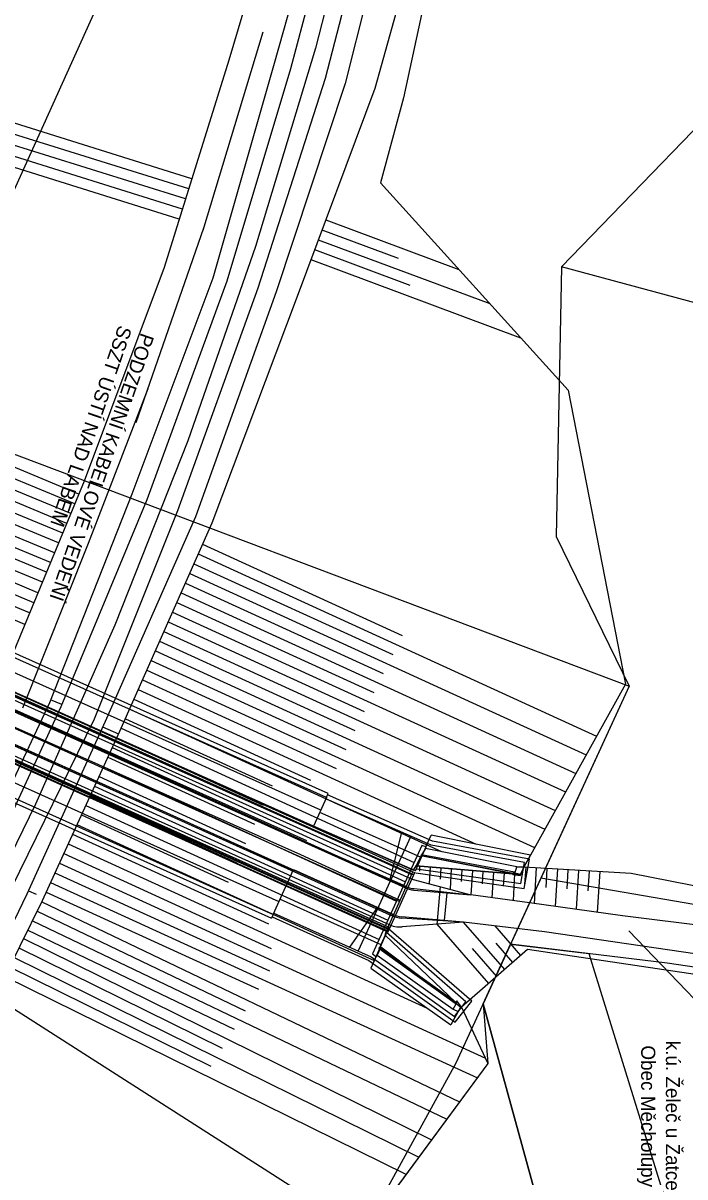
# Model space of a CAD drawing. Extents: x -801372 to -800991, y -1017235 to -1016862.
# Drawn here: x -801119.6 to -801072.7, y -1017078.6 to -1016996.8 of the extents above; entities that cross this region are included whole.
import ezdxf

# ---------------------------------------------------------------- set-up
doc = ezdxf.new("R2010")
doc.units = 0
for name, color, linetype in [('01 - nosná konstrukce', 7, 'Continuous'), ('02 - spodní stavba', 7, 'Continuous'), ('05a - kolej - svršek', 7, 'Continuous'), ('09 - stávající terén', 7, 'Continuous'), ('10 - nový terén', 7, 'Continuous'), ('15 - popisy', 7, 'Continuous'), ('16 - osy', 7, 'Continuous'), ('19 - katastr', 7, 'Continuous'), ('19b - katastr - hranice SŽDC', 7, 'Continuous'), ('19b - katastr popisy', 7, 'Continuous'), ('21g - SZDC', 7, 'Continuous'), ('26 - obvod_stavby', 7, 'Continuous'), ('27 - dočasné zábory', 7, 'Continuous'), ('Vrstva 1 - kolej', 7, 'Continuous'), ('Vrstva 48 - svahy', 7, 'Continuous')]:
    doc.layers.add(name, color=color, linetype=linetype)

msp = doc.modelspace()

# ---------------------------------------------------------------- linework, layer by layer
for points in [[(-801079.49, -1017062.745), (-801060.39, -1017124.37)], [(-801086.965, -1017066.29), (-801072.61, -1017118.61)]]:
    msp.add_lwpolyline(points)
at = {"layer": '01 - nosná konstrukce'}
for p, q in [((-801141.511, -1017034.878), (-801092.044, -1017057.15)), ((-801141.489, -1017034.828), (-801092.021, -1017057.1)), ((-801143.243, -1017038.724), (-801093.775, -1017060.996)), ((-801143.22, -1017038.674), (-801093.753, -1017060.945)), ((-801092.021, -1017057.1), (-801093.775, -1017060.996))]:
    msp.add_line(p, q, dxfattribs=at)
at = {"layer": '02 - spodní stavba'}
for p, q in [((-801141.627, -1017035.135), (-801092.117, -1017057.424)), ((-801141.422, -1017034.679), (-801091.954, -1017056.95)), ((-801097.948, -1017051.409), (-801131.185, -1017036.524)), ((-801098.071, -1017051.683), (-801131.308, -1017036.798)), ((-801098.473, -1017052.582), (-801131.711, -1017037.697)), ((-801143.31, -1017038.874), (-801093.842, -1017061.145)), ((-801143.067, -1017038.435), (-801093.637, -1017060.689)), ((-801099.101, -1017053.983), (-801132.338, -1017039.098)), ((-801132.255, -1017038.823), (-801099.018, -1017053.686)), ((-801098.978, -1017053.709), (-801132.215, -1017038.824)), ((-801099.45, -1017054.763), (-801132.687, -1017039.878)), ((-801133.146, -1017040.902), (-801099.914, -1017055.737)), ((-801100.984, -1017057.895), (-801134.364, -1017042.851)), ((-801133.986, -1017042.769), (-801100.807, -1017057.665)), ((-801098.112, -1017051.774), (-801097.948, -1017051.409)), ((-801098.071, -1017051.683), (-801098.978, -1017053.709)), ((-801090.658, -1017055.067), (-801098.112, -1017051.774)), ((-801090.569, -1017054.778), (-801097.988, -1017051.501)), ((-801091.422, -1017055.91), (-801098.548, -1017052.762)), ((-801099.018, -1017053.686), (-801091.898, -1017056.845)), ((-801091.774, -1017056.891), (-801098.978, -1017053.709)), ((-801091.899, -1017057.164), (-801099.099, -1017053.983)), ((-801092.103, -1017054.428), (-801095.817, -1017062.559)), ((-801093.559, -1017057.485), (-801092.729, -1017054.152)), ((-801092.421, -1017057.988), (-801099.479, -1017054.87)), ((-801091.774, -1017056.891), (-801090.917, -1017054.952)), ((-801091.066, -1017055.291), (-801091.353, -1017055.786)), ((-801091.066, -1017055.291), (-801091.019, -1017055.182)), ((-801084.598, -1017056.601), (-801091.066, -1017055.291)), ((-801084.039, -1017056.299), (-801090.658, -1017055.067)), ((-801083.689, -1017056.059), (-801090.569, -1017054.778)), ((-801099.914, -1017055.737), (-801099.905, -1017055.716)), ((-801099.905, -1017055.716), (-801092.864, -1017058.972)), ((-801091.347, -1017055.752), (-801091.714, -1017056.522)), ((-801091.347, -1017055.752), (-801091.379, -1017055.802)), ((-801091.353, -1017055.786), (-801091.379, -1017055.802)), ((-801091.379, -1017055.802), (-801084.812, -1017057.096)), ((-801091.353, -1017055.786), (-801084.738, -1017057.07)), ((-801084.752, -1017056.98), (-801091.347, -1017055.752)), ((-801084.316, -1017057.786), (-801084.039, -1017056.299)), ((-801084.073, -1017058.124), (-801083.689, -1017056.059)), ((-801101.839, -1017059.964), (-801100.41, -1017056.785)), ((-801100.411, -1017056.785), (-801093.316, -1017059.972)), ((-801093.706, -1017061.206), (-801091.817, -1017057.012)), ((-801092.021, -1017057.1), (-801091.954, -1017056.95)), ((-801091.954, -1017056.95), (-801091.817, -1017057.012)), ((-801091.827, -1017057.007), (-801091.899, -1017057.164)), ((-801091.898, -1017056.845), (-801091.714, -1017056.522)), ((-801091.747, -1017057.031), (-801084.073, -1017058.124)), ((-801091.714, -1017056.522), (-801084.296, -1017057.142)), ((-801091.704, -1017056.734), (-801084.316, -1017057.786)), ((-801084.877, -1017057.154), (-801084.851, -1017057.028)), ((-801084.851, -1017057.028), (-801084.752, -1017056.98)), ((-801084.296, -1017057.142), (-801084.851, -1017057.028)), ((-801084.812, -1017057.096), (-801084.752, -1017056.98)), ((-801084.812, -1017057.096), (-801084.738, -1017057.07)), ((-801084.738, -1017057.07), (-801084.598, -1017056.601)), ((-801084.738, -1017057.07), (-801084.332, -1017057.125)), ((-801084.598, -1017056.601), (-801084.097, -1017056.612)), ((-801084.332, -1017057.125), (-801084.36, -1017057.216)), ((-801084.36, -1017057.216), (-801084.296, -1017057.142)), ((-801084.097, -1017056.612), (-801084.332, -1017057.125)), ((-801084.296, -1017057.142), (-801084.097, -1017056.612)), ((-801093.829, -1017061.114), (-801100.984, -1017057.895)), ((-801100.807, -1017057.665), (-801093.642, -1017060.883)), ((-801101.355, -1017058.887), (-801094.212, -1017062.097)), ((-801094.46, -1017059.458), (-801096.442, -1017062.279)), ((-801101.839, -1017059.964), (-801101.962, -1017060.237)), ((-801101.798, -1017059.872), (-801094.909, -1017062.968)), ((-801093.923, -1017061.442), (-801093.829, -1017061.114)), ((-801093.775, -1017060.996), (-801093.842, -1017061.145)), ((-801093.842, -1017061.145), (-801093.706, -1017061.206)), ((-801088.198, -1017066.161), (-801093.813, -1017061.259)), ((-801093.642, -1017060.883), (-801093.768, -1017061.156)), ((-801087.786, -1017066.123), (-801093.689, -1017060.986)), ((-801093.923, -1017061.442), (-801094.341, -1017062.39)), ((-801088.898, -1017066.209), (-801093.923, -1017061.442)), ((-801094.226, -1017062.286), (-801094.486, -1017062.862)), ((-801094.486, -1017062.862), (-801089.094, -1017066.688)), ((-801094.341, -1017062.39), (-801094.311, -1017062.284)), ((-801094.341, -1017062.39), (-801088.947, -1017066.254)), ((-801094.311, -1017062.284), (-801088.857, -1017066.199)), ((-801094.226, -1017062.286), (-801094.311, -1017062.284)), ((-801088.889, -1017066.293), (-801094.226, -1017062.286)), ((-801094.909, -1017062.968), (-801089.013, -1017067.191)), ((-801094.624, -1017063.095), (-801094.748, -1017063.369)), ((-801089.013, -1017067.191), (-801088.198, -1017066.161)), ((-801089.094, -1017066.688), (-801088.889, -1017066.293)), ((-801089.094, -1017066.688), (-801088.739, -1017066.845)), ((-801088.947, -1017066.254), (-801088.898, -1017066.209)), ((-801088.857, -1017066.199), (-801088.889, -1017066.293)), ((-801088.571, -1017066.549), (-801088.889, -1017066.293)), ((-801088.571, -1017066.549), (-801088.739, -1017066.845)), ((-801088.501, -1017066.544), (-801088.571, -1017066.549))]:
    msp.add_line(p, q, dxfattribs=at)
for points in [[(-801144.304, -1017041.012), (-801143.355, -1017038.895), (-801134.109, -1017043.043), (-801100.929, -1017057.938), (-801093.768, -1017061.156), (-801094.624, -1017063.095)], [(-801133.635, -1017041.989), (-801100.456, -1017056.885)], [(-801134.614, -1017044.17), (-801101.435, -1017059.065)], [(-801135.14, -1017045.342), (-801101.962, -1017060.237)], [(-801135.017, -1017045.068), (-801101.839, -1017059.964)], [(-801091.898, -1017056.845), (-801091.908, -1017056.832)], [(-801084.812, -1017057.096), (-801084.877, -1017057.154), (-801084.36, -1017057.216)], [(-801101.921, -1017060.146), (-801095.059, -1017063.229), (-801088.955, -1017067.602), (-801087.786, -1017066.123)], [(-801093.844, -1017061.123), (-801093.829, -1017061.114)], [(-801088.947, -1017066.254), (-801088.857, -1017066.199), (-801088.847, -1017066.095)], [(-801088.501, -1017066.544), (-801088.847, -1017066.095), (-801088.898, -1017066.209)]]:
    msp.add_lwpolyline(points, dxfattribs=at)
at = {"layer": '05a - kolej - svršek'}
for p, q in [((-801097.681, -1016985.202), (-801101.815, -1016999.87)), ((-801096.694, -1016985.292), (-801100.623, -1017000.081)), ((-801094.326, -1016985.96), (-801098.17, -1017000.765)), ((-801093.001, -1016986.187), (-801096.751, -1017001.133)), ((-801101.815, -1016999.87), (-801106.12, -1017014.918)), ((-801100.623, -1017000.081), (-801105.127, -1017015.126)), ((-801098.17, -1017000.765), (-801102.922, -1017015.627)), ((-801096.751, -1017001.133), (-801101.624, -1017015.873)), ((-801106.12, -1017014.918), (-801111.843, -1017030.203)), ((-801105.127, -1017015.126), (-801110.785, -1017030.615)), ((-801102.922, -1017015.627), (-801108.608, -1017031.382)), ((-801101.624, -1017015.873), (-801107.351, -1017031.811)), ((-801111.843, -1017030.203), (-801117.691, -1017044.978)), ((-801110.785, -1017030.615), (-801116.869, -1017045.275)), ((-801108.608, -1017031.382), (-801114.526, -1017046.136)), ((-801107.351, -1017031.811), (-801113.747, -1017046.297)), ((-801117.691, -1017044.978), (-801123.526, -1017057.407)), ((-801116.869, -1017045.275), (-801122.516, -1017057.485)), ((-801114.526, -1017046.136), (-801120.402, -1017058.145)), ((-801113.747, -1017046.297), (-801119.29, -1017058.542)), ((-801119.29, -1017058.542), (-801126.271, -1017073.005))]:
    msp.add_line(p, q, dxfattribs=at)
at = {"layer": '09 - stávající terén'}
for p, q in [((-801100.678, -1016984.915), (-801104.977, -1016999.48)), ((-801090.496, -1016986.553), (-801094.657, -1017001.481)), ((-801089.247, -1016986.662), (-801092.622, -1017002.134)), ((-801104.977, -1016999.48), (-801109.562, -1017014.148)), ((-801094.657, -1017001.481), (-801100.153, -1017016.222)), ((-801092.622, -1017002.134), (-801094.239, -1017008.166)), ((-801094.239, -1017008.166), (-801080.961, -1017022.847)), ((-801109.562, -1017014.148), (-801115.218, -1017029.281)), ((-801100.153, -1017016.222), (-801106.182, -1017032.263)), ((-801080.961, -1017022.847), (-801076.897, -1017043.673)), ((-801115.218, -1017029.281), (-801121.19, -1017043.671)), ((-801106.182, -1017032.263), (-801112.715, -1017047.005)), ((-801076.897, -1017043.673), (-801084.097, -1017056.612)), ((-801112.715, -1017047.005), (-801118.207, -1017059.007)), ((-801091.319, -1017055.086), (-801094.8, -1017062.766)), ((-801091.019, -1017055.182), (-801091.319, -1017055.086)), ((-801091.066, -1017055.291), (-801091.019, -1017055.182)), ((-801084.598, -1017056.601), (-801091.066, -1017055.291)), ((-801091.898, -1017056.845), (-801091.714, -1017056.522)), ((-801084.296, -1017057.142), (-801091.714, -1017056.522)), ((-801084.097, -1017056.612), (-801084.598, -1017056.601)), ((-801084.097, -1017056.612), (-801084.296, -1017057.142)), ((-801076.495, -1017057.077), (-801084.097, -1017056.612)), ((-801062.231, -1017059.889), (-801076.495, -1017057.077)), ((-801083.693, -1017059.143), (-801087.84, -1017058.59)), ((-801118.207, -1017059.007), (-801125.337, -1017073.453)), ((-801077.117, -1017060.061), (-801083.693, -1017059.143)), ((-801062.815, -1017061.841), (-801077.117, -1017060.061)), ((-801093.829, -1017061.114), (-801093.923, -1017061.442)), ((-801082.636, -1017061.197), (-801088.356, -1017060.529)), ((-801066.831, -1017063.534), (-801082.636, -1017061.197)), ((-801088.898, -1017066.209), (-801093.923, -1017061.442)), ((-801094.8, -1017062.766), (-801094.535, -1017062.971)), ((-801094.535, -1017062.971), (-801094.486, -1017062.862)), ((-801094.486, -1017062.862), (-801089.094, -1017066.688)), ((-801083.827, -1017062.453), (-801088.501, -1017066.544)), ((-801067.033, -1017064.948), (-801083.827, -1017062.453)), ((-801088.847, -1017066.095), (-801088.898, -1017066.209)), ((-801088.501, -1017066.544), (-801088.847, -1017066.095)), ((-801089.094, -1017066.688), (-801088.739, -1017066.845)), ((-801088.739, -1017066.845), (-801088.501, -1017066.544)), ((-801088.501, -1017066.544), (-801086.638, -1017070.523)), ((-801086.638, -1017070.523), (-801096.55, -1017083.938))]:
    msp.add_line(p, q, dxfattribs=at)
at = {"layer": '10 - nový terén'}
for p, q in [((-801141.939, -1017035.828), (-801092.528, -1017058.074)), ((-801141.898, -1017035.737), (-801092.487, -1017057.982)), ((-801142.834, -1017037.816), (-801093.366, -1017060.087)), ((-801142.793, -1017037.725), (-801093.393, -1017059.965)), ((-801090.98, -1017055.094), (-801090.653, -1017054.354)), ((-801083.632, -1017055.776), (-801090.653, -1017054.354)), ((-801084.097, -1017056.612), (-801083.632, -1017055.776)), ((-801091.92, -1017057.493), (-801087.84, -1017058.59)), ((-801090.019, -1017058.004), (-801090.258, -1017060.672)), ((-801091.879, -1017058.242), (-801087.84, -1017058.59)), ((-801091.87, -1017058.143), (-801087.84, -1017058.59)), ((-801089.556, -1017058.444), (-801089.732, -1017060.405)), ((-801088.356, -1017060.529), (-801092.76, -1017060.233)), ((-801088.356, -1017060.529), (-801092.751, -1017060.134)), ((-801088.356, -1017060.529), (-801092.709, -1017060.856)), ((-801094.549, -1017062.925), (-801094.927, -1017063.775)), ((-801094.927, -1017063.775), (-801089.274, -1017067.787)), ((-801088.571, -1017066.549), (-801089.274, -1017067.787))]:
    msp.add_line(p, q, dxfattribs=at)
for centre, radius, start, end in [((-801091.707, -1017056.25), 1.9, 245.76194, 265.07504), ((-801091.608, -1017056.293), 1.24, 245.76194, 255.41849), ((-801091.707, -1017056.25), 2, 245.76194, 265.07504), ((-801092.572, -1017058.142), 2.1, 245.76194, 264.86349), ((-801092.572, -1017058.142), 2, 245.76194, 264.86349), ((-801092.838, -1017058.895), 1.965, 243.82234, 273.77815)]:
    msp.add_arc(centre, radius, start, end, dxfattribs=at)
at = {"layer": '15 - popisy'}
msp.add_lwpolyline([(-801116.389, -1017036.889), (-801116.288, -1017037.065), (-801116.441, -1017036.932)], close=True, dxfattribs=at)
at = {"layer": '16 - osy'}
msp.add_line((-801142.366, -1017036.776), (-801092.898, -1017059.048), dxfattribs=at)
at = {"layer": '19 - katastr'}
msp.add_line((-801082.88, -1017057.4), (-801085.03, -1017062.08), dxfattribs=at)
for points in [[(-800990.795, -1017053.756), (-801000.61, -1017041.98), (-801042.92, -1017041.79), (-801045.15, -1017030.95), (-801044.91, -1017020.07), (-801069.54, -1017017.32), (-801081.43, -1017014.11)], [(-801033.76, -1017064.4), (-801041.29, -1017061.79), (-801049.51, -1017062.6), (-801066.15, -1017060.28), (-801082.88, -1017057.4)], [(-800990.795, -1017106.782), (-800998.64, -1017106.06), (-801013.25, -1017105.09), (-801017.99, -1017102.9), (-801022.81, -1017094.66), (-801025.28, -1017087.9), (-801037.51, -1017074.11), (-801039.25, -1017068.41), (-801041.9, -1017066.94), (-801053.83, -1017066.4), (-801073.95, -1017063.41), (-801085.03, -1017062.08)]]:
    msp.add_lwpolyline(points, dxfattribs=at)
at = {"layer": '19b - katastr - hranice SŽDC'}
for points in [[(-801065.05, -1016959.48), (-801066.45, -1016998.62), (-801081.43, -1017014.11)], [(-801146.17, -1017027.77), (-801131.4, -1017034.56), (-801122.73, -1017014.27), (-801103.54, -1016971.8), (-801099.44, -1016966.34), (-801099.01, -1016964.03), (-801100.45, -1016961.93)], [(-801081.43, -1017014.11), (-801081.81, -1017033.2), (-801076.63, -1017043.81), (-801082.88, -1017057.4)], [(-801085.03, -1017062.08), (-801088.9, -1017070.5), (-801105.75, -1017101.2)]]:
    msp.add_lwpolyline(points, dxfattribs=at)
at = {"layer": '19b - katastr popisy'}
msp.add_line((-801069.69, -1017068.413), (-801076.661, -1017061.127), dxfattribs=at)
at = {"layer": '21g - SZDC'}
for p, q in [((-801102.578, -1016997.501), (-801106.814, -1017011.535)), ((-801106.767, -1017011.379), (-801111.561, -1017025.158)), ((-801110.724, -1017022.75), (-801114.948, -1017033.699)), ((-801114.948, -1017033.699), (-801119.589, -1017045.36))]:
    msp.add_line(p, q, dxfattribs=at)
at = {"layer": '26 - obvod_stavby'}
for points in [[(-801141.216, -1017053.254), (-801148.66, -1017042.443), (-801151.48, -1017039.58), (-801150.013, -1017036.785), (-801149.01, -1017037.86), (-801147.484, -1017032.446), (-801147.484, -1017032.446), (-801146.17, -1017027.77), (-801146.17, -1017027.77), (-801144.517, -1017019.826), (-801132.211, -1017024.121), (-801127.204, -1017024.741), (-801076.63, -1017043.81), (-801086.965, -1017066.29)], [(-801085.002, -1017062.083), (-801079.49, -1017062.745), (-801060.39, -1017124.37), (-801060.39, -1017137.347), (-801071.855, -1017135.755), (-801072.61, -1017118.61), (-801086.965, -1017066.29), (-801086.638, -1017070.523), (-801095.483, -1017082.494), (-801141.216, -1017053.254), (-801148.66, -1017042.443), (-801151.48, -1017039.58)]]:
    msp.add_lwpolyline(points, dxfattribs=at)
at = {"layer": '27 - dočasné zábory'}
msp.add_lwpolyline([(-801072.61, -1017118.61), (-801086.965, -1017066.29), (-801085.03, -1017062.08), (-801079.49, -1017062.745), (-801060.39, -1017124.37), (-801072.61, -1017118.61)], dxfattribs=at)
at = {"layer": 'Vrstva 1 - kolej'}
for p, q in [((-801095.397, -1016985.106), (-801098.848, -1016998.627)), ((-801098.848, -1016998.627), (-801103.084, -1017012.661)), ((-801103.084, -1017012.661), (-801107.878, -1017026.44)), ((-801107.878, -1017026.44), (-801113.048, -1017039.492)), ((-801113.048, -1017039.492), (-801118.67, -1017052.166)), ((-801118.67, -1017052.166), (-801124.852, -1017064.76))]:
    msp.add_line(p, q, dxfattribs=at)
at = {"layer": 'Vrstva 48 - svahy'}
for p, q in [((-801107.6, -1017007.872), (-801138.6, -1016998.182)), ((-801108.048, -1017009.304), (-801140.297, -1016999.223)), ((-801108.495, -1017010.735), (-801141.994, -1017000.264)), ((-801107.824, -1017008.588), (-801123.636, -1017003.645)), ((-801108.271, -1017010.019), (-801124.709, -1017004.881)), ((-801098.125, -1017010.782), (-801088.693, -1017014.298)), ((-801098.649, -1017012.187), (-801086.509, -1017016.713)), ((-801098.387, -1017011.484), (-801092.994, -1017013.495)), ((-801098.911, -1017012.89), (-801092.163, -1017015.405)), ((-801099.173, -1017013.592), (-801084.324, -1017019.129)), ((-801115.601, -1017030.203), (-801148.438, -1017016.575)), ((-801116.176, -1017031.588), (-801148.683, -1017018.097)), ((-801116.75, -1017032.974), (-801148.982, -1017019.597)), ((-801117.325, -1017034.359), (-801149.281, -1017021.097)), ((-801117.9, -1017035.744), (-801149.58, -1017022.597)), ((-801118.503, -1017037.196), (-801149.596, -1017024.216)), ((-801115.888, -1017030.895), (-801132.211, -1017024.121)), ((-801119.096, -1017038.624), (-801149.131, -1017026.039)), ((-801116.463, -1017032.281), (-801132.648, -1017025.564)), ((-801117.038, -1017033.666), (-801133.085, -1017027.007)), ((-801117.613, -1017035.052), (-801133.522, -1017028.449)), ((-801118.188, -1017036.437), (-801133.958, -1017029.892)), ((-801118.795, -1017037.899), (-801134.079, -1017031.513)), ((-801119.438, -1017039.449), (-801134.185, -1017033.135)), ((-801106.846, -1017033.761), (-801092.712, -1017040.228)), ((-801107.453, -1017035.132), (-801093.382, -1017041.571)), ((-801107.15, -1017034.446), (-801078.945, -1017047.353)), ((-801107.757, -1017035.818), (-801079.676, -1017048.667)), ((-801108.061, -1017036.504), (-801094.052, -1017042.914)), ((-801108.365, -1017037.189), (-801080.408, -1017049.982)), ((-801108.669, -1017037.875), (-801094.721, -1017044.257)), ((-801108.973, -1017038.561), (-801081.139, -1017051.297)), ((-801109.581, -1017039.932), (-801081.871, -1017052.612)), ((-801109.277, -1017039.246), (-801095.391, -1017045.6)), ((-801109.885, -1017040.618), (-801096.061, -1017046.944)), ((-801110.188, -1017041.304), (-801082.603, -1017053.927)), ((-801110.492, -1017041.989), (-801096.7, -1017048.3)), ((-801110.796, -1017042.675), (-801083.334, -1017055.241)), ((-801111.404, -1017044.047), (-801087.468, -1017054.999)), ((-801111.1, -1017043.361), (-801097.378, -1017049.64)), ((-801116.8, -1017045.108), (-801117.61, -1017044.772)), ((-801111.708, -1017044.732), (-801099.191, -1017050.46)), ((-801111.993, -1017045.427), (-801089.936, -1017055.52)), ((-801112.305, -1017046.109), (-801101.926, -1017050.858)), ((-801113.921, -1017046.682), (-801112.799, -1017047.189)), ((-801112.617, -1017046.791), (-801091.859, -1017056.29)), ((-801113.241, -1017048.155), (-801092.483, -1017057.654)), ((-801112.929, -1017047.473), (-801102.55, -1017052.222)), ((-801113.553, -1017048.837), (-801103.173, -1017053.587)), ((-801113.865, -1017049.519), (-801093.102, -1017059.02)), ((-801114.177, -1017050.201), (-801103.794, -1017054.952)), ((-801114.489, -1017050.883), (-801093.721, -1017060.386)), ((-801115.114, -1017052.247), (-801094.345, -1017061.75)), ((-801114.801, -1017051.565), (-801104.417, -1017056.316)), ((-801115.426, -1017052.929), (-801105.042, -1017057.68)), ((-801115.738, -1017053.611), (-801094.69, -1017063.242)), ((-801116.05, -1017054.293), (-801102.17, -1017060.644)), ((-801116.362, -1017054.975), (-801090.928, -1017066.613)), ((-801116.986, -1017056.339), (-801086.815, -1017070.144)), ((-801116.674, -1017055.657), (-801101.99, -1017062.376)), ((-801117.298, -1017057.021), (-801102.114, -1017063.969)), ((-801091.472, -1017056.542), (-801091.494, -1017056.906)), ((-801090.724, -1017056.605), (-801090.797, -1017057.795)), ((-801089.977, -1017056.667), (-801090.026, -1017057.48)), ((-801089.229, -1017056.73), (-801089.319, -1017058.193)), ((-801088.481, -1017056.792), (-801088.533, -1017057.642)), ((-801087.734, -1017056.855), (-801087.84, -1017058.59)), ((-801086.986, -1017056.917), (-801087.04, -1017057.803)), ((-801086.239, -1017056.98), (-801086.349, -1017058.789)), ((-801085.491, -1017057.042), (-801085.548, -1017057.965)), ((-801084.744, -1017057.105), (-801084.859, -1017058.988)), ((-801083.963, -1017056.62), (-801084.038, -1017057.854)), ((-801083.214, -1017056.666), (-801083.368, -1017059.188)), ((-801082.465, -1017056.712), (-801082.548, -1017058.06)), ((-801081.717, -1017056.758), (-801081.878, -1017059.396)), ((-801080.968, -1017056.803), (-801081.051, -1017058.152)), ((-801080.22, -1017056.849), (-801080.388, -1017059.604)), ((-801079.471, -1017056.895), (-801079.557, -1017058.302)), ((-801078.722, -1017056.941), (-801078.898, -1017059.812)), ((-801117.61, -1017057.703), (-801087.385, -1017071.533)), ((-801119.179, -1017058.297), (-801118.638, -1017058.542)), ((-801117.922, -1017058.385), (-801102.881, -1017065.267)), ((-801118.234, -1017059.067), (-801088.64, -1017073.232)), ((-801118.882, -1017060.42), (-801089.548, -1017074.461)), ((-801118.558, -1017059.743), (-801103.826, -1017066.795)), ((-801119.206, -1017061.096), (-801104.604, -1017068.086)), ((-801086.567, -1017064.851), (-801090.227, -1017060.669)), ((-801085.438, -1017063.863), (-801088.356, -1017060.529)), ((-801084.309, -1017062.875), (-801086.136, -1017060.788)), ((-801119.519, -1017061.664), (-801090.628, -1017075.924)), ((-801084.873, -1017063.369), (-801086.06, -1017062.014)), ((-801119.851, -1017062.337), (-801105.466, -1017069.437)), ((-801086.002, -1017064.357), (-801087.734, -1017062.378)), ((-801120.514, -1017063.682), (-801106.251, -1017070.722)), ((-801120.182, -1017063.01), (-801091.534, -1017077.149)), ((-801120.846, -1017064.355), (-801092.44, -1017078.375))]:
    msp.add_line(p, q, dxfattribs=at)

# ---------------------------------------------------------------- texts
at = {"layer": '19b - katastr popisy'}
for s, p in [('Obec Měcholupy', (-801075.786, -1017069.245)), ('k.ú. Želeč u Žatce ', (-801074.035, -1017068.915))]:
    msp.add_text(s, height=1.00005, rotation=270, dxfattribs=at).set_placement(p)
at = {"layer": '21g - SZDC'}
for s, p in [('SSZT ÚSTÍ NAD LABEM', (-801112.775, -1017018.189)), ('PODZEMNÍ KABELOVÉ VEDENÍ ', (-801111.2, -1017018.733))]:
    msp.add_text(s, height=1, rotation=250.95195, dxfattribs=at).set_placement(p)

doc.saveas('drawing.dxf')
